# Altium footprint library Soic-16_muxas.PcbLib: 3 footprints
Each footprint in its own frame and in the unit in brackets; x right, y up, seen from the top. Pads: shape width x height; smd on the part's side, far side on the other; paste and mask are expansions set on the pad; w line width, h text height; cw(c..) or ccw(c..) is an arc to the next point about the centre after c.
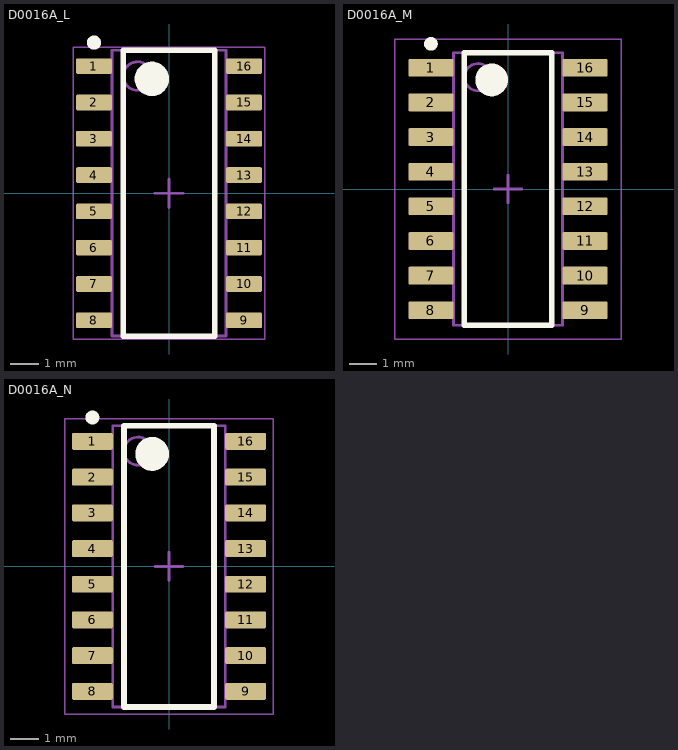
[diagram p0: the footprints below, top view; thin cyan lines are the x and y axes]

## D0016A_L [mm] "SOIC, 16-Leads, Body 10x4mm, Pitch 1.27mm, IPC High Density"
height 1.75
pads (16):
  rrect18% 1.25x0.55 smd: 1(-2.625,4.445) 2(-2.625,3.175) 3(-2.625,1.905) 4(-2.625,0.635) 5(-2.625,-0.635) 6(-2.625,-1.905) 7(-2.625,-3.175) 8(-2.625,-4.445) 9(2.625,-4.445) 10(2.625,-3.175) 11(2.625,-1.905) 12(2.625,-0.635) 13(2.625,0.635) 14(2.625,1.905) 15(2.625,3.175) 16(2.625,4.445)
Top Overlay:
  circle w0.25: c-2.625,5.27 r0.125
  circle w0.6: c-0.6,4 r0.3
  lines w0.2: -1.6,-5 -1.6,5 1.6,5 1.6,-5 -1.6,-5
Mechanical 1:
  text ".Designator" at -1.531,-0.319 h0.8
Mechanical 13:
  circle w0.1: c-1.1,4.1 r0.5
  lines w0.1: -2,-5 -2,5 2,5 2,-5 -2,-5
Mechanical 15:
  lines w0.05: -3.35,-5.1 -3.35,5.1 3.35,5.1 3.35,-5.1 -3.35,-5.1
  lines w0.1: -0.5,0 0.5,0 ; 0,-0.5 0,0.5
3D body "SOIC-16akaD0016AakaM16A.stp": height 1.59, standoff -0.01, extent -2.997,-4.953 2.997,4.953

## D0016A_M [mm] "SOIC, 16-Leads, Body 10x4mm, Pitch 1.27mm, IPC Low Density"
height 1.75
pads (16):
  rrect15% 1.65x0.65 smd: 1(-2.825,4.445) 2(-2.825,3.175) 3(-2.825,1.905) 4(-2.825,0.635) 5(-2.825,-0.635) 6(-2.825,-1.905) 7(-2.825,-3.175) 8(-2.825,-4.445) 9(2.825,-4.445) 10(2.825,-3.175) 11(2.825,-1.905) 12(2.825,-0.635) 13(2.825,0.635) 14(2.825,1.905) 15(2.825,3.175) 16(2.825,4.445)
Top Overlay:
  circle w0.25: c-2.825,5.32 r0.125
  circle w0.6: c-0.6,4 r0.3
  lines w0.2: -1.6,-5 -1.6,5 1.6,5 1.6,-5 -1.6,-5
Mechanical 1:
  text ".Designator" at -1.575,-0.35 h0.8
Mechanical 13:
  circle w0.1: c-1.1,4.1 r0.5
  lines w0.1: -2,-5 -2,5 2,5 2,-5 -2,-5
Mechanical 15:
  lines w0.05: -4.15,-5.5 -4.15,5.5 4.15,5.5 4.15,-5.5 -4.15,-5.5
  lines w0.1: -0.5,0 0.5,0 ; 0,-0.5 0,0.5
3D body "SOIC-16akaD0016AakaM16A.stp": height 1.59, standoff -0.01, extent -2.997,-4.953 2.997,4.953

## D0016A_N [mm] "SOIC, 16-Leads, Body 10x4mm, Pitch 1.27mm, IPC Medium Density"
height 1.75
pads (16):
  rrect17% 1.45x0.6 smd: 1(-2.725,4.445) 2(-2.725,3.175) 3(-2.725,1.905) 4(-2.725,0.635) 5(-2.725,-0.635) 6(-2.725,-1.905) 7(-2.725,-3.175) 8(-2.725,-4.445) 9(2.725,-4.445) 10(2.725,-3.175) 11(2.725,-1.905) 12(2.725,-0.635) 13(2.725,0.635) 14(2.725,1.905) 15(2.725,3.175) 16(2.725,4.445)
Top Overlay:
  circle w0.6: c-0.6,4 r0.3
  circle w0.25: c-2.725,5.295 r0.125
  lines w0.2: -1.6,-5 1.6,-5 1.6,5 -1.6,5 -1.6,-5
Mechanical 1:
  text ".Designator" at -1.575,-0.275 h0.8
Mechanical 13:
  circle w0.1: c-1.1,4.1 r0.5
  lines w0.1: -2,-5 2,-5 2,5 -2,5 -2,-5
Mechanical 15:
  lines w0.05: -3.7,-5.25 3.7,-5.25 3.7,5.25 -3.7,5.25 -3.7,-5.25
  lines w0.1: -0.5,0 0.5,0 ; 0,-0.5 0,0.5
3D body "SOIC-16akaD0016AakaM16A.stp": height 1.59, standoff -0.01, extent -2.997,-4.953 2.997,4.953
